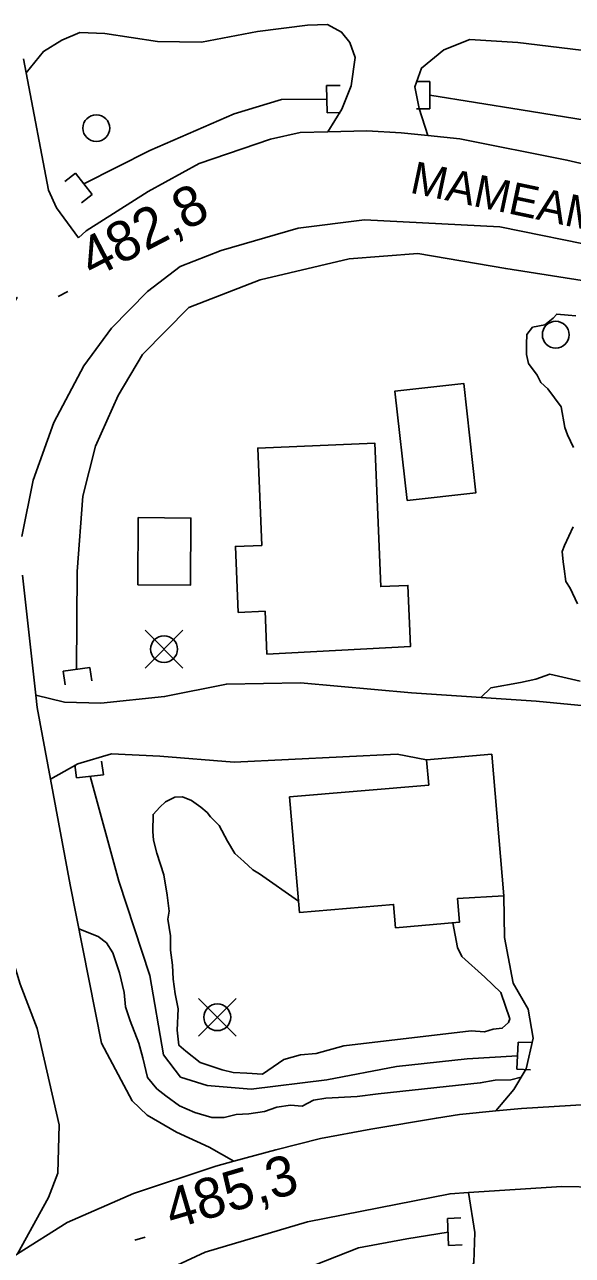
# Model space of a CAD drawing. Extents: x 642515 to 647219, y 6080136 to 6084356.
# Drawn here: x 643545.5 to 643586.4, y 6082088.1 to 6082179.9 of the extents above; entities that cross this region are included whole.
import ezdxf

# ---------------------------------------------------------------- set-up
doc = ezdxf.new("R2010")
doc.units = 0
for name, color, linetype in [('Level 19', 7, 'Continuous'), ('Level 2', 7, 'Continuous'), ('Level 21', 7, 'Continuous'), ('Level 26', 7, 'Continuous'), ('Level 3', 7, 'Continuous'), ('Level 31', 7, 'Continuous'), ('Level 36', 7, 'Continuous'), ('Level 4', 7, 'Continuous')]:
    doc.layers.add(name, color=color, linetype=linetype)

msp = doc.modelspace()

# ---------------------------------------------------------------- linework, layer by layer
at = {"layer": 'Level 19'}
for points in [[(643545.567, 6082176.259), (643546.855, 6082177.868), (643548.227, 6082178.71), (643549.575, 6082179.267), (643551.446, 6082179.202), (643555.375, 6082178.595), (643558.664, 6082178.563), (643562.838, 6082179.348), (643566.584, 6082179.826), (643568.083, 6082179.864), (643569.129, 6082179.31), (643569.742, 6082178.531), (643570.13, 6082177.415), (643569.845, 6082175.292), (643569.133, 6082173.551), (643568.093, 6082171.864)], [(643575.573, 6082171.582), (643574.93, 6082173.617), (643574.594, 6082175.222), (643575.082, 6082176.626), (643576.751, 6082177.97), (643578.694, 6082178.76), (643582.276, 6082178.541), (643587.831, 6082177.857), (643593.196, 6082176.96), (643598.512, 6082175.493), (643601.388, 6082174.143), (643602.637, 6082172.87), (643603.576, 6082171.337), (643603.672, 6082169.639), (643603.036, 6082167.984), (643601.827, 6082166.172)], [(643617.745, 6082157.256), (643617.206, 6082154.594), (643616.404, 6082150.864), (643615.227, 6082145.173), (643613.298, 6082137.016), (643612.666, 6082132.448), (643611.311, 6082129.908), (643608.881, 6082127.029), (643606.959, 6082126.605), (643602.388, 6082127.177), (643594.295, 6082128.376), (643583.658, 6082129.402), (643574.34, 6082130.011), (643566.068, 6082130.755), (643560.519, 6082130.669), (643555.91, 6082129.741), (643551.153, 6082129.251), (643548.433, 6082129.312), (643546.284, 6082129.839)], [(643547.382, 6082123.566), (643549.424, 6082124.725), (643551.937, 6082125.464), (643555.556, 6082125.287), (643561.096, 6082124.846), (643573.266, 6082125.439), (643575.476, 6082125.023)], [(643581.236, 6082114.877), (643581.292, 6082111.763), (643581.932, 6082108.355), (643583.055, 6082106.43), (643583.422, 6082104.263), (643582.904, 6082101.97), (643581.979, 6082100.424), (643580.65, 6082098.831)], [(643570.27, 6082080.035), (643569.587, 6082083.475), (643573.481, 6082084.041), (643576.627, 6082084.973), (643577.967, 6082085.609), (643578.5, 6082086.203), (643578.992, 6082087.522), (643579.067, 6082089.75), (643578.613, 6082092.737)]]:
    msp.add_lwpolyline(points, dxfattribs=at)
at = {"layer": 'Level 2'}
for points in [[(643586.612, 6082158.143), (643586.044, 6082158.193), (643585.192, 6082158.268), (643584.925, 6082157.974), (643584.306, 6082157.461), (643583.386, 6082157.292), (643582.97, 6082156.75), (643582.927, 6082156.026), (643582.927, 6082155.265), (643583.083, 6082154.592), (643583.736, 6082153.705), (643584.007, 6082153.159), (643584.515, 6082152.705), (643585.514, 6082151.356), (643585.798, 6082149.809), (643585.988, 6082149.258), (643586.441, 6082148.321)], [(643586.429, 6082142.394), (643585.776, 6082140.998), (643585.597, 6082140.548), (643585.677, 6082139.792), (643585.745, 6082139.275), (643585.876, 6082138.321), (643586.185, 6082137.817), (643586.731, 6082136.644)], [(643586.952, 6082130.892), (643584.664, 6082131.412), (643583.634, 6082131.037), (643582.477, 6082130.777), (643580.278, 6082130.381), (643579.525, 6082129.672)], [(643577.427, 6082112.853), (643577.775, 6082111.021), (643578.093, 6082110.358), (643579.829, 6082108.809), (643581.018, 6082107.672), (643581.687, 6082105.707), (643581.581, 6082105.421), (643581.119, 6082104.997), (643580.437, 6082104.921), (643579.801, 6082104.728), (643578.789, 6082104.794), (643569.284, 6082103.694), (643567.217, 6082103.106), (643566.052, 6082103.004), (643564.819, 6082102.66), (643563.222, 6082101.576), (643562.049, 6082101.634), (643561.036, 6082101.701), (643560.219, 6082101.898), (643558.575, 6082102.451), (643557.483, 6082103.274), (643556.974, 6082103.727), (643556.835, 6082104.839), (643556.911, 6082106.444), (643556.691, 6082107.552), (643556.552, 6082108.665), (643556.497, 6082109.702), (643556.357, 6082110.815), (643556.34, 6082111.894), (643556.154, 6082113.125), (643556.243, 6082113.729), (643556.099, 6082114.922), (643555.858, 6082116.43), (643555.329, 6082118.043), (643555.075, 6082119.03), (643555.041, 6082119.668), (643555.054, 6082120.949), (643555.549, 6082121.496), (643555.973, 6082121.878), (643556.681, 6082122.236), (643557.244, 6082122.265), (643557.905, 6082121.98), (643558.617, 6082121.497), (643559.083, 6082121.081), (643559.341, 6082120.775), (643559.981, 6082120.128), (643560.608, 6082118.961), (643561.142, 6082118.028), (643561.819, 6082117.424), (643562.497, 6082116.819), (643562.997, 6082116.525), (643565.9, 6082114.469)], [(643582.531, 6082101.346), (643581.765, 6082101.151), (643580.596, 6082101.13), (643579.478, 6082100.911), (643571.853, 6082100.11), (643570.29, 6082099.908), (643567.957, 6082099.785), (643567.038, 6082099.617), (643566.173, 6082099.171), (643565.322, 6082099.247), (643564.28, 6082099.112), (643563.369, 6082098.784), (643562.209, 6082098.603), (643561.243, 6082098.552), (643560.366, 6082098.346), (643559.439, 6082098.337), (643558.168, 6082098.71), (643557.012, 6082099.209), (643556.004, 6082099.956), (643555.331, 6082100.481), (643554.64, 6082101.324), (643554.28, 6082102.785), (643553.98, 6082103.889), (643553.328, 6082105.535), (643552.989, 6082106.597), (643552.891, 6082107.672), (643552.531, 6082109.133), (643552.049, 6082110.628), (643551.566, 6082111.363), (643550.935, 6082111.85), (643549.494, 6082112.421)]]:
    msp.add_lwpolyline(points, dxfattribs=at)
at = {"layer": 'Level 21'}
for points in [[(643545.367, 6082177.313), (643545.567, 6082176.259), (643547.228, 6082167.511), (643547.831, 6082166.203), (643549.483, 6082163.968)], [(643659.173, 6082143.779), (643656.353, 6082145.617), (643653.571, 6082147.158), (643647.396, 6082150.58), (643646.432, 6082151.027), (643637.486, 6082155.17), (643625.848, 6082160.157), (643613.819, 6082163.423), (643609.832, 6082164.344), (643603.788, 6082165.74), (643601.827, 6082166.172), (643594.255, 6082167.84), (643585.949, 6082169.76), (643577.945, 6082171.331), (643575.573, 6082171.582), (643573.577, 6082171.794), (643571.011, 6082171.944), (643568.093, 6082171.864), (643566.027, 6082171.807), (643563.822, 6082171.327), (643558.487, 6082169.509), (643554.67, 6082167.404), (643550.046, 6082164.486), (643549.483, 6082163.968)], [(643545.248, 6082141.671), (643546.102, 6082145.891), (643547.641, 6082150.187), (643549.875, 6082154.398), (643551.945, 6082157.223), (643554.63, 6082159.958), (643557.08, 6082161.829), (643560.138, 6082163.002), (643565.887, 6082164.68), (643570.844, 6082165.303), (643580.938, 6082164.773), (643588.779, 6082163.193), (643601.875, 6082160.509), (643616.439, 6082157.658), (643617.745, 6082157.256), (643623.361, 6082155.527), (643629.732, 6082153.566), (643636.323, 6082151.242), (643639.745, 6082150.035), (643650.941, 6082144.905), (643656.153, 6082141.612), (643658.672, 6082139.354), (643661.178, 6082135.881)], [(643544.892, 6082159.513), (643544.892, 6082159.513), (643542.992, 6082156.535), (643541.451, 6082150.858), (643540.452, 6082144.927), (643540.227, 6082141.148), (643539.981, 6082135.542), (643540.26, 6082127.859), (643541.518, 6082120.067), (643542.239, 6082117.7), (643545.113, 6082108.273), (643546.396, 6082104.981), (643548.024, 6082097.786), (643547.947, 6082094.183), (643547.947, 6082094.183), (643547.242, 6082092.369), (643544.932, 6082088.166)], [(643561.087, 6082095.079), (643559.245, 6082096.121), (643556.791, 6082097.247), (643554.612, 6082098.509), (643553.497, 6082099.584), (643551.186, 6082103.873), (643548.847, 6082115.691), (643547.382, 6082123.566), (643546.385, 6082128.925), (643546.284, 6082129.839), (643545.291, 6082138.796)], [(643541.232, 6082085.671), (643544.932, 6082088.166), (643548.643, 6082090.501), (643553.579, 6082092.657), (643559.736, 6082094.716), (643561.087, 6082095.079), (643564.203, 6082095.918), (643567.562, 6082096.771), (643571.317, 6082097.477), (643576.212, 6082098.298), (643577.929, 6082098.571), (643580.65, 6082098.831), (643582.562, 6082099.014), (643587.448, 6082099.309), (643591.672, 6082099.269)], [(643626.587, 6082087.323), (643617.065, 6082089.498), (643605.894, 6082091.465), (643594.912, 6082092.957), (643588.186, 6082093.132), (643585.581, 6082093.2), (643578.613, 6082092.737), (643577.228, 6082092.645), (643566.574, 6082090.554), (643558.93, 6082088.296), (643550.887, 6082084.564)]]:
    msp.add_lwpolyline(points, dxfattribs=at)
at = {"layer": 'Level 26'}
for p, q in [((643568.01, 6082175.31), (643569.01, 6082175.33)), ((643568.05, 6082173.29), (643568.01, 6082175.31)), ((643575.72, 6082175.61), (643574.72, 6082175.61)), ((643575.72, 6082175.61), (643575.72, 6082173.59)), ((643568.05, 6082173.29), (643569.05, 6082173.31)), ((643575.72, 6082173.59), (643574.72, 6082173.59)), ((643549.25, 6082168.77), (643548.47, 6082168.15)), ((643549.25, 6082168.77), (643550.51, 6082167.19)), ((643550.51, 6082167.19), (643549.71, 6082166.57)), ((643548.34, 6082131.62), (643550.32, 6082131.9)), ((643548.34, 6082131.62), (643548.48, 6082130.62)), ((643550.32, 6082131.9), (643550.48, 6082130.92)), ((643549.32, 6082123.67), (643549.2, 6082124.65)), ((643551.34, 6082123.91), (643551.2, 6082124.91)), ((643551.34, 6082123.91), (643549.32, 6082123.67)), ((643582.22, 6082101.94), (643582.3, 6082103.96)), ((643582.3, 6082103.96), (643583.3, 6082103.92)), ((643582.22, 6082101.94), (643583.22, 6082101.9)), ((643577.04, 6082090.81), (643578.04, 6082090.85)), ((643577.12, 6082088.79), (643577.04, 6082090.81)), ((643577.12, 6082088.79), (643578.12, 6082088.83))]:
    msp.add_line(p, q, dxfattribs=at)
at = {"layer": 'Level 3'}
for p, q in [((643547.969, 6082159.585), (643548.679, 6082159.952)), ((643553.692, 6082089.195), (643554.46, 6082089.421))]:
    msp.add_line(p, q, dxfattribs=at)
at = {"layer": 'Level 31'}
for points in [[(643574.015, 6082144.367), (643573.104, 6082152.525), (643578.248, 6082153.1), (643579.159, 6082144.941), (643574.015, 6082144.367)], [(643563.546, 6082132.897), (643563.413, 6082136.102), (643561.404, 6082136.019), (643561.201, 6082140.937), (643563.157, 6082141.018), (643562.858, 6082148.271), (643571.612, 6082148.632), (643572.053, 6082137.945), (643574.075, 6082138.028), (643574.263, 6082133.468), (643563.546, 6082132.897)], [(643553.903, 6082138.065), (643553.939, 6082143.083), (643557.872, 6082143.054), (643557.836, 6082138.037), (643553.903, 6082138.065)], [(643581.236, 6082114.877), (643580.34, 6082125.436), (643575.476, 6082125.023), (643575.637, 6082123.128), (643565.239, 6082122.246), (643565.971, 6082113.629), (643573.009, 6082114.226), (643573.156, 6082112.494), (643577.927, 6082112.899), (643577.777, 6082114.67), (643581.236, 6082114.877)]]:
    msp.add_lwpolyline(points, dxfattribs=at)
at = {"layer": 'Level 36'}
for p, q in [((643557.27, 6082131.86), (643554.45, 6082134.68)), ((643554.45, 6082131.86), (643557.27, 6082134.68)), ((643561.25, 6082104.4), (643558.43, 6082107.22)), ((643558.43, 6082104.4), (643561.25, 6082107.22))]:
    msp.add_line(p, q, dxfattribs=at)
for centre in [(643550.808, 6082172.14), (643585.118, 6082156.73), (643555.864, 6082133.275), (643559.844, 6082105.815)]:
    msp.add_circle(centre, 1, dxfattribs=at)
at = {"layer": 'Level 4'}
for points in [[(643549.874, 6082167.994), (643554.81, 6082170.483), (643561.115, 6082173.206), (643564.628, 6082174.282), (643568.027, 6082174.292)], [(643575.722, 6082174.611), (643582.528, 6082173.503), (643589.004, 6082172.46), (643596.139, 6082170.518), (643602.419, 6082169.103)], [(643549.318, 6082131.761), (643549.386, 6082139.064), (643549.795, 6082144.684), (643550.758, 6082148.426), (643552.451, 6082152.207), (643554.266, 6082155.263), (643557.721, 6082158.771), (643563.044, 6082160.833), (643569.696, 6082162.396), (643574.831, 6082162.784), (643581.39, 6082161.665), (643588.845, 6082160.511), (643592.428, 6082159.949)], [(643582.264, 6082102.938), (643578.507, 6082102.702), (643573.228, 6082102.144), (643568.014, 6082101.144), (643562.378, 6082100.446), (643559.078, 6082100.72), (643557.097, 6082101.346), (643555.825, 6082103.021), (643554.797, 6082108.92), (643552.487, 6082115.97), (643550.343, 6082123.79)], [(643526.425, 6082037.466), (643521.136, 6082040.979), (643518.785, 6082042.549), (643517.962, 6082043.513), (643517.75, 6082044.389), (643518.055, 6082046.097), (643519.147, 6082048.169), (643521.068, 6082050.567), (643524.529, 6082056.391), (643528.113, 6082060.813), (643532.775, 6082066.18), (643536.285, 6082069.834), (643539.439, 6082072.663), (643543.443, 6082075.497), (643546.57, 6082078.124), (643551.023, 6082080.943), (643554.854, 6082082.638), (643558.386, 6082083.914), (643564.647, 6082086.343), (643570.392, 6082088.624), (643574.001, 6082089.297), (643577.077, 6082089.789)]]:
    msp.add_lwpolyline(points, dxfattribs=at)

# ---------------------------------------------------------------- texts
at = {"layer": 'Level 21'}
msp.add_text('MAMEAMSKUM', height=2.4, rotation=348.11268, dxfattribs=at).set_placement((643574.15, 6082167.34))
at = {"layer": 'Level 3'}
for s, rotation, p in [('482,8', 27.38303, (643550.54, 6082160.88)), ('485,3', 16.41511, (643556.47, 6082089.97))]:
    msp.add_text(s, height=3, rotation=rotation, dxfattribs=at).set_placement(p)

doc.saveas('drawing.dxf')
